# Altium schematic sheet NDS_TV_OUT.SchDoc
size A3; CompanyName: KDS; Organization: KDS; DocumentNumber: 0; Revision: V1I1; SheetNumber: 0; SheetTotal: 5; PageSetup: Record=PageOptions¦CenterHorizontal=True¦CenterVertical=True¦PrintScale=1.07¦XCorrection=1.00¦YCorrection=1.00¦PrintKind=1¦BorderSize=5000000¦LeftOffset=0¦BottomOffset=0¦Orientation=2¦PaperLength=1000¦PaperWidth=1000¦Scale=100¦PaperSource=7¦PrintQuality=600¦MediaType=1¦DitherType=10¦PaperKind=A3¦PrintScaleMode=1
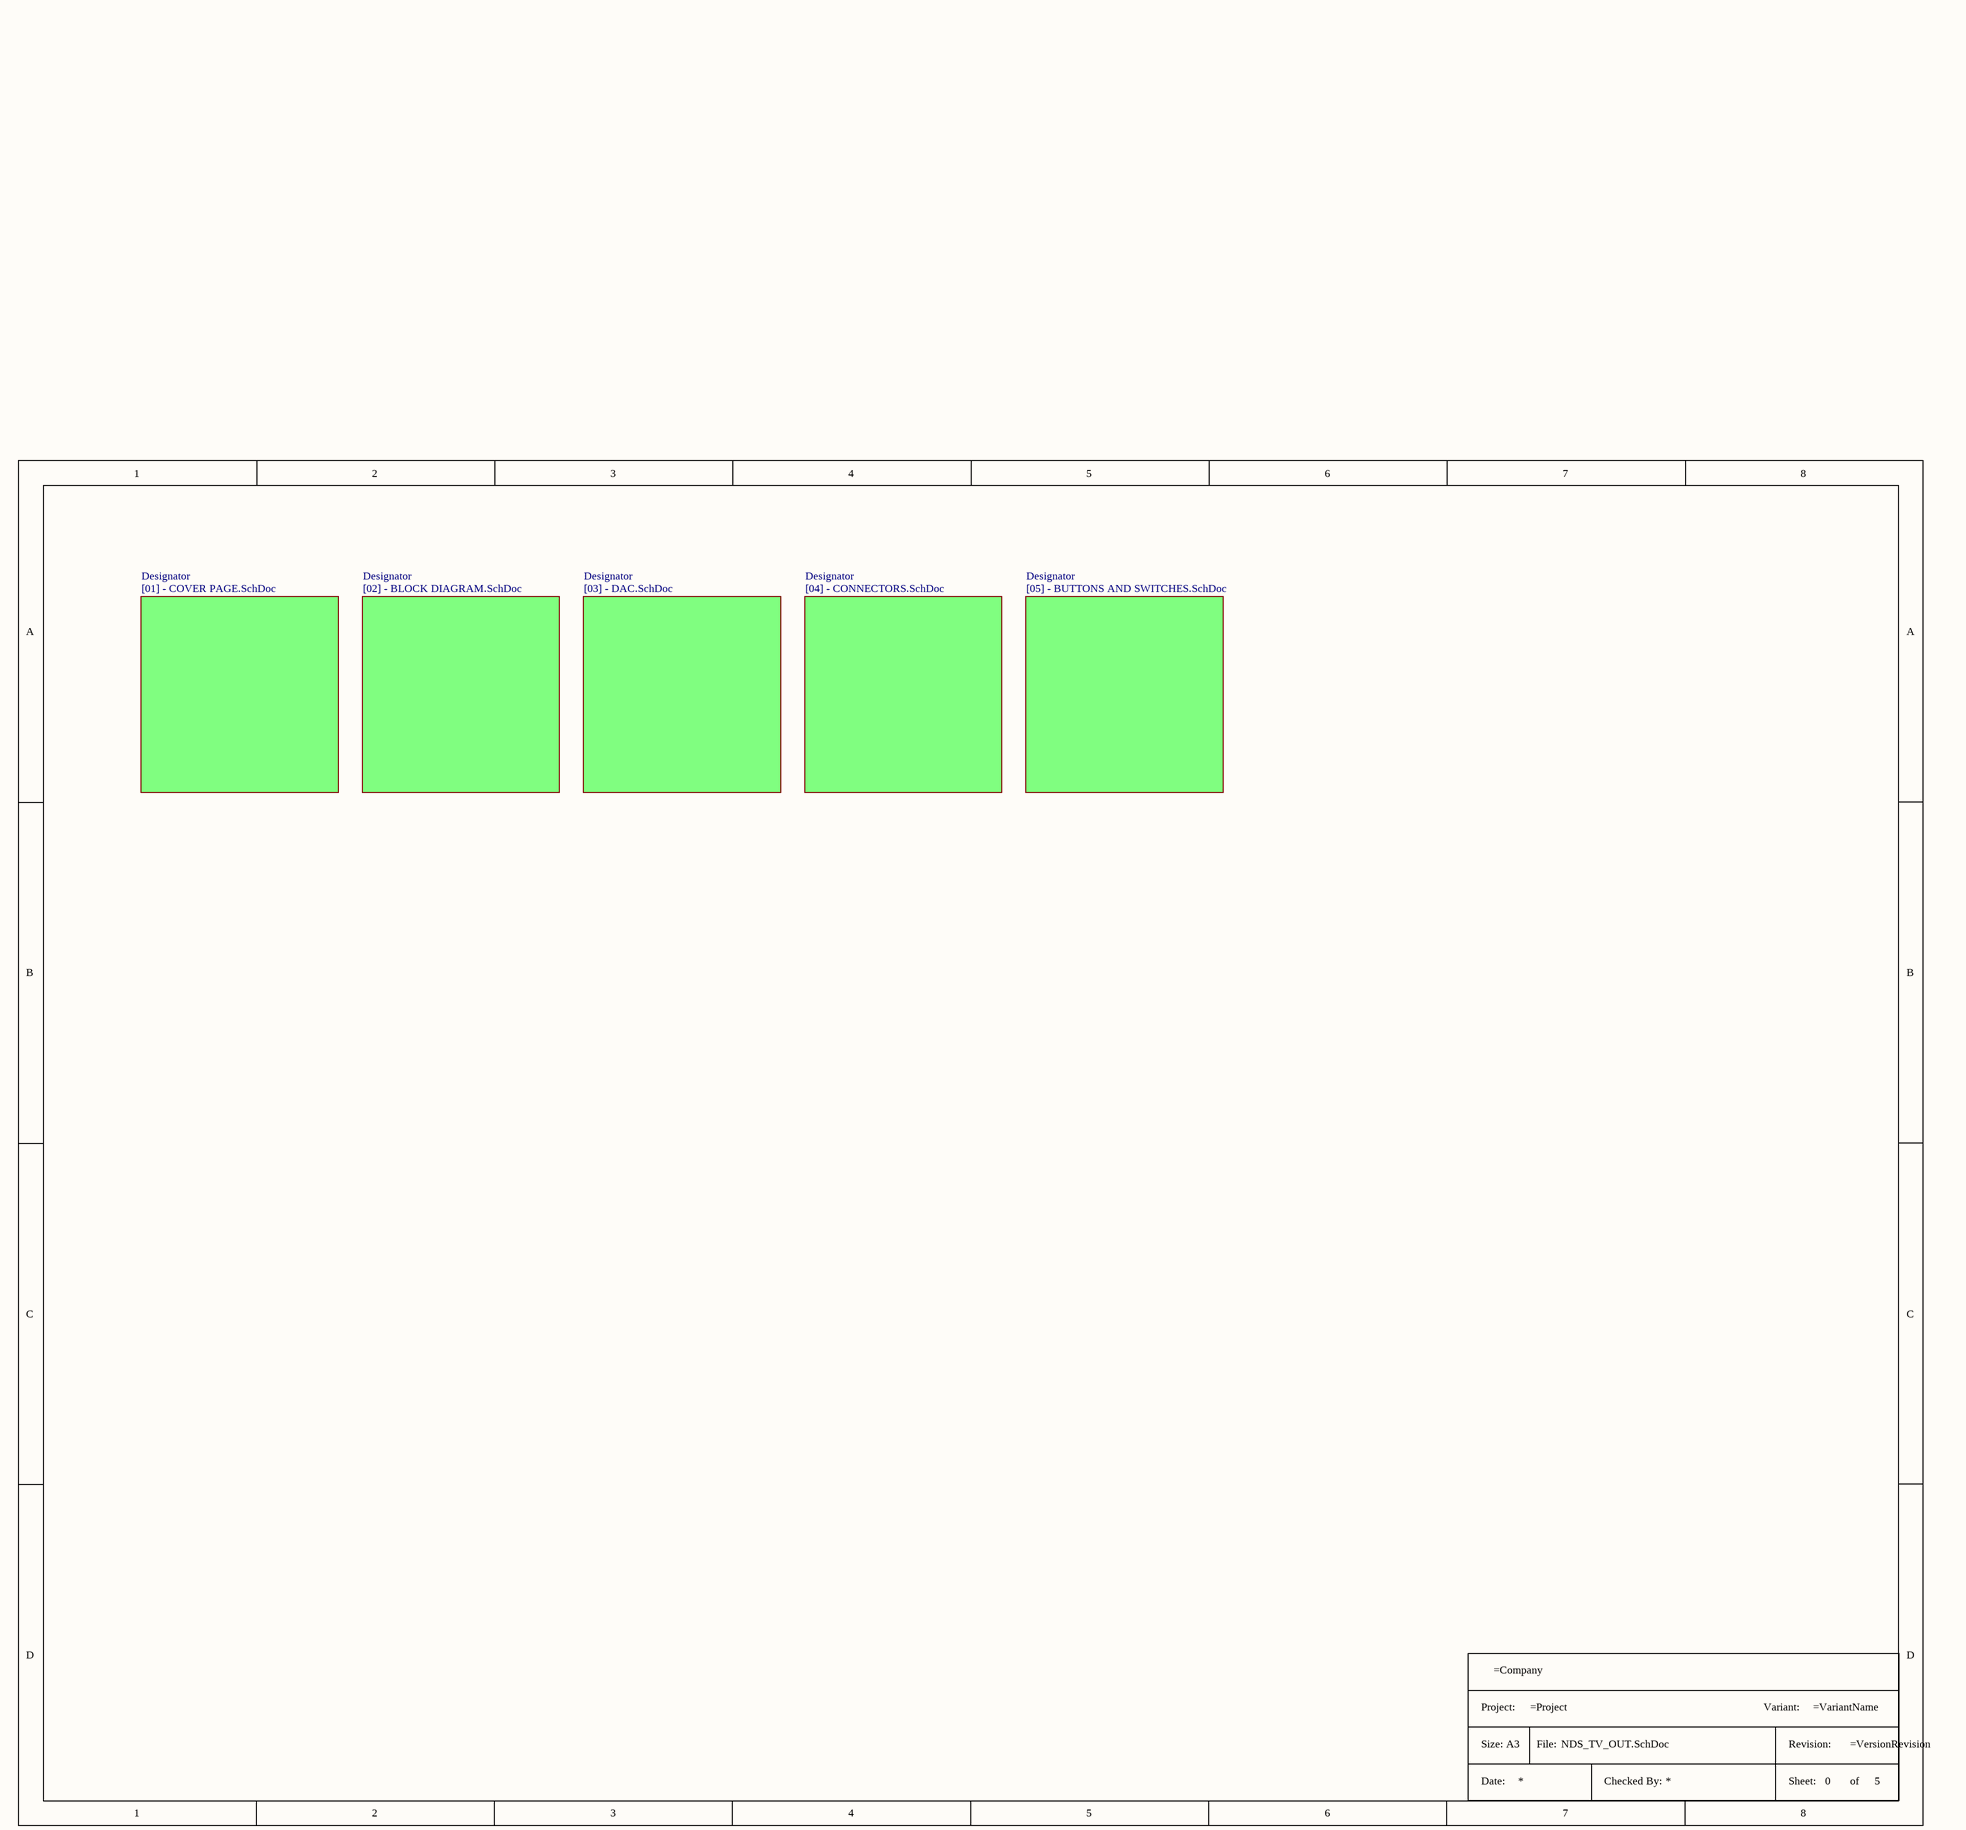
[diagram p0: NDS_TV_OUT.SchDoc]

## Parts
*  Title Block A3  (value not drawn)  (graphical)

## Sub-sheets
Designator = [01] - COVER PAGE.SchDoc: no entries
Designator = [02] - BLOCK DIAGRAM.SchDoc: no entries
Designator = [03] - DAC.SchDoc: no entries
Designator = [04] - CONNECTORS.SchDoc: no entries
Designator = [05] - BUTTONS AND SWITCHES.SchDoc: no entries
